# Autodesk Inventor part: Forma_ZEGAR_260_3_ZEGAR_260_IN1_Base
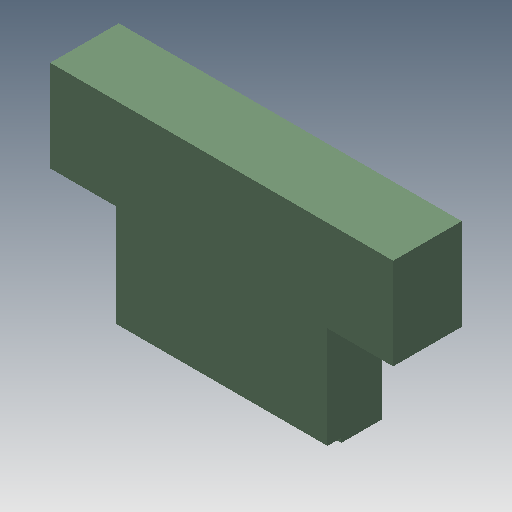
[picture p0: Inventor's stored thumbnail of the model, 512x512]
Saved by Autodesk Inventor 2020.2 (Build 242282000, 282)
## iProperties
Created: 2015-01
Part Number: Forma_ZEGAR_260_3_ZEGAR_260_IN1_Base
Material: Ogólny
Document SubType Name: Modeling
Designer: F.Stasiak
Density: 1 g/cm^3
Appearance: Domyślna
Catalog Web Link: www.expertbooks.pl
Manager: www.cadconsulting.pl
Company: Fabian Stasiak CAD Consulting
Author: F.Stasiak
Subject: Zbiór ćwiczeń. Autodesk Inventor 2020. Kurs Professional
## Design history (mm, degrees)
node "Forma_ZEGAR_260_3_ZEGAR_260_MP"
feature "Bryła5::Forma_ZEGAR_260_3_ZEGAR_260_MP"
tag "Bryła wyprowadzona1"
node "Bryła1"
feature "Forma_ZEGAR_260_3_ZEGAR_260_MP_Bodies"
